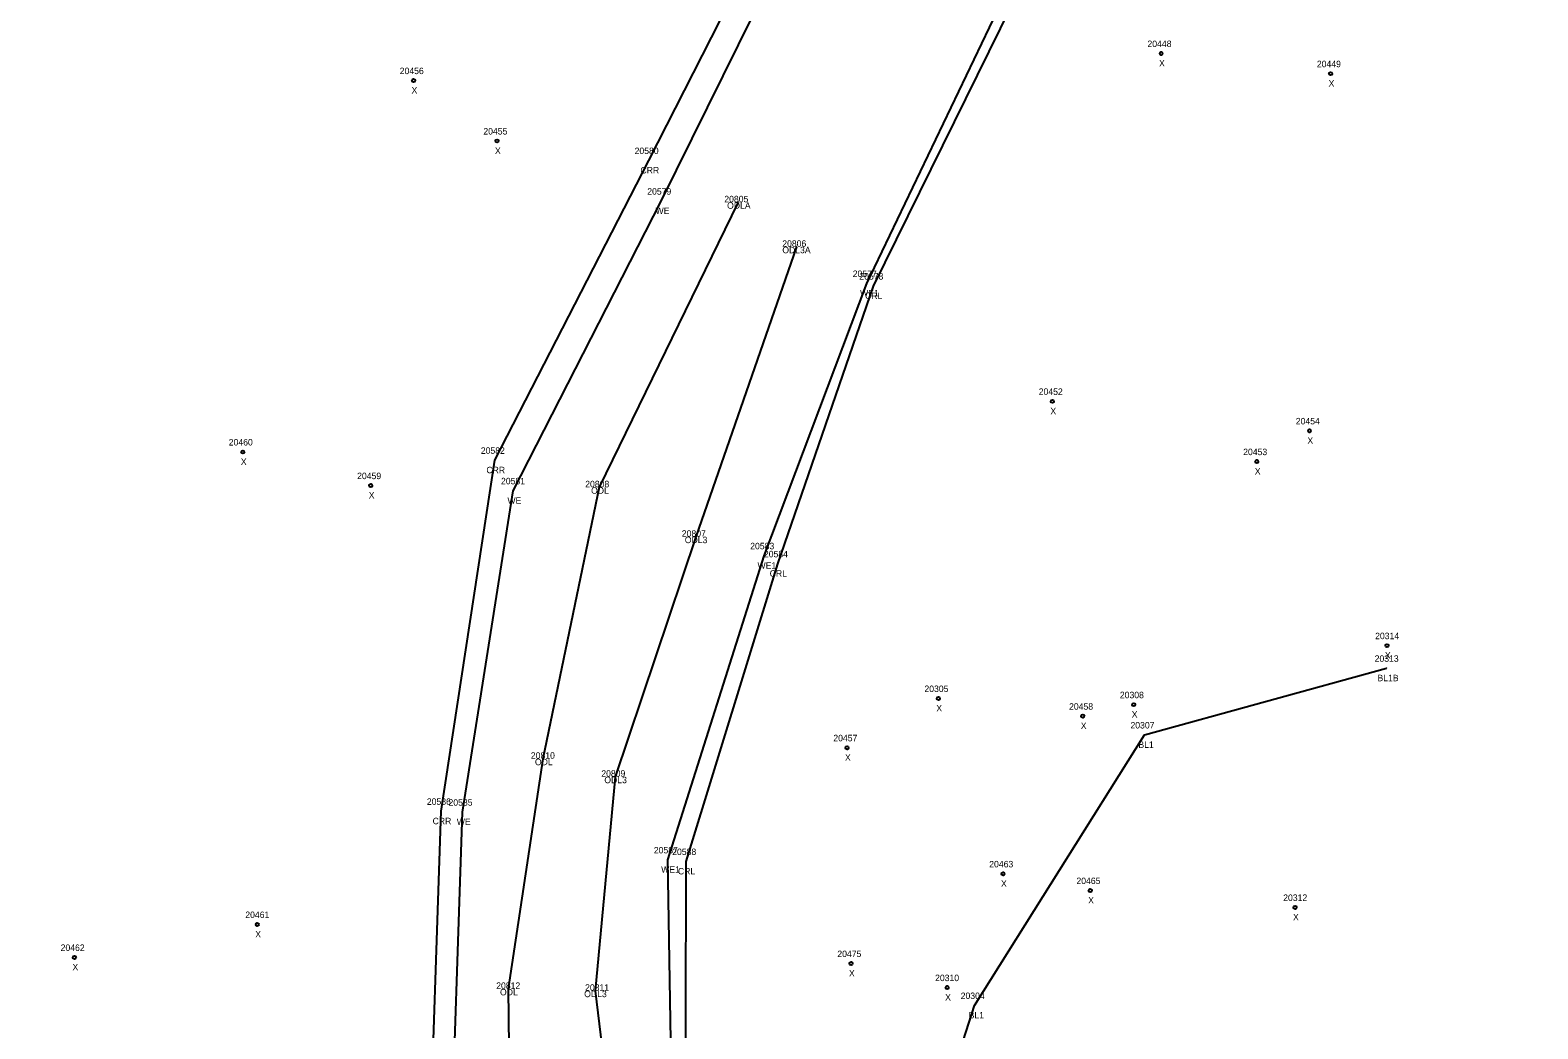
# Model space of a CAD drawing. Extents: x 1966740 to 1969291, y 1117378 to 1118461.
# Drawn here: x 1967728.3 to 1967961.6, y 1117958.8 to 1118113.2 of the extents above; entities that cross this region are included whole.
import ezdxf

# ---------------------------------------------------------------- set-up
doc = ezdxf.new("R2010")
doc.units = 0
for name, color, linetype in [('RD_DTM_BkLn1', 7, 'Continuous'), ('RD_EX_H2O', 7, 'Continuous'), ('RD_EX_H2O_txCode', 7, 'Continuous'), ('RD_SMD_Locator', 7, 'Continuous'), ('RD_SMD_Misc', 7, 'Continuous')]:
    doc.layers.add(name, color=color, linetype=linetype)

msp = doc.modelspace()

# ---------------------------------------------------------------- linework, layer by layer
at = {"layer": 'RD_DTM_BkLn1'}
msp.add_lwpolyline([(1967864.65, 1117932.01), (1967874.44, 1117962.38), (1967900.7, 1118004.22), (1967938.17, 1118014.53)], dxfattribs=at)
at = {"layer": 'RD_EX_H2O'}
for points in [[(1967852.4, 1118390.04), (1967912.21, 1118383.64), (1967925.08, 1118336.82), (1967944.14, 1118294.4), (1967946.67, 1118243.15), (1967961.58, 1118191.28), (1967922.84, 1118148.62), (1967880.18, 1118117.11), (1967858.72, 1118073.64), (1967843.96, 1118030.69), (1967829.77, 1117984.65), (1967829.63, 1117934.73), (1967834.65, 1117903.36)], [(1967852.05, 1118385.41), (1967898.77, 1118376.41), (1967924.08, 1118337.23), (1967939.81, 1118294.93), (1967943.5, 1118242.16), (1967952.29, 1118191.75), (1967920.83, 1118149.81), (1967879.07, 1118118.61), (1967857.7, 1118074.04), (1967841.84, 1118031.93), (1967826.93, 1117984.9), (1967827.73, 1117935.27), (1967832.39, 1117902.59), (1967835.81, 1117893.8), (1967842.37, 1117871.73), (1967853.33, 1117857.05), (1967865.72, 1117824.99), (1967870.38, 1117810.73), (1967864.06, 1117791.33)], [(1967848.72, 1118350.07), (1967881.79, 1118342.06), (1967895.58, 1118338.92), (1967907.43, 1118282.36), (1967910.66, 1118232.56), (1967917.99, 1118192.64), (1967910.91, 1118176.45), (1967849.83, 1118135.18), (1967825.91, 1118086.77), (1967802.99, 1118041.98), (1967795.15, 1117992.28), (1967793.27, 1117935.35), (1967800.64, 1117889.8), (1967800.4, 1117872.52), (1967800.8, 1117854.99), (1967811.67, 1117837.73), (1967837.15, 1117809.04), (1967808.01, 1117752.12)], [(1967848.54, 1118347.45), (1967880.38, 1118337.78), (1967886.93, 1118331.58), (1967896.4, 1118282.85), (1967906.33, 1118232.39), (1967914.38, 1118193.81), (1967904.29, 1118181.59), (1967847.52, 1118139.25), (1967823.99, 1118093.05), (1967800.15, 1118046.69), (1967791.83, 1117992.41), (1967789.93, 1117935.61), (1967798.32, 1117889.19), (1967796.67, 1117880.97)], [(1967837.87, 1118086.59), (1967816.35, 1118042.52), (1967807.65, 1118000.54), (1967802.25, 1117964.95), (1967802.7, 1117929.05), (1967808.24, 1117891.66), (1967818.1, 1117847.27), (1967841.92, 1117812.91), (1967830.83, 1117773.47), (1967807.55, 1117730.13), (1967792.1, 1117688.21), (1967759.2, 1117626.42), (1967746.8, 1117597.58), (1967728.31, 1117575.82), (1967748.97, 1117519.79), (1967787.59, 1117491.86), (1967802.7, 1117484.72), (1967813.63, 1117479.24)], [(1967846.86, 1118079.71), (1967831.29, 1118034.88), (1967818.84, 1117997.76), (1967815.72, 1117964.67), (1967820.18, 1117928.06), (1967829.19, 1117896.79), (1967834.11, 1117854.1), (1967863.47, 1117815.02), (1967842.32, 1117765.95), (1967826.02, 1117725.1), (1967807.77, 1117682.35), (1967775.42, 1117611.81), (1967754.74, 1117587.12), (1967745.94, 1117565.65), (1967761.23, 1117525.28), (1967787.1, 1117502.15), (1967805.18, 1117494.11), (1967821.41, 1117490.36)]]:
    msp.add_lwpolyline(points, dxfattribs=at)
at = {"layer": 'RD_SMD_Locator'}
for centre, radius in [((1967903.3, 1118109.6), 0.25), ((1967929.51, 1118106.48), 0.25), ((1967787.64, 1118105.41), 0.25), ((1967800.55, 1118096.07), 0.25), ((1967823.99, 1118093.05), 0.001), ((1967825.91, 1118086.77), 0.001), ((1967837.87, 1118086.59), 0.001), ((1967846.86, 1118079.71), 0.001), ((1967857.7, 1118074.04), 0.001), ((1967858.72, 1118073.64), 0.001), ((1967886.47, 1118055.81), 0.25), ((1967926.25, 1118051.25), 0.25), ((1967761.22, 1118047.98), 0.25), ((1967800.15, 1118046.69), 0.001), ((1967918.1, 1118046.49), 0.25), ((1967781.01, 1118042.78), 0.25), ((1967802.99, 1118041.98), 0.001), ((1967816.35, 1118042.52), 0.001), ((1967831.29, 1118034.88), 0.001), ((1967841.84, 1118031.93), 0.001), ((1967843.96, 1118030.69), 0.001), ((1967938.24, 1118018.03), 0.25), ((1967938.17, 1118014.53), 0.001), ((1967868.83, 1118009.86), 0.25), ((1967899.06, 1118008.9), 0.25), ((1967891.17, 1118007.13), 0.25), ((1967900.7, 1118004.22), 0.001), ((1967854.7, 1118002.24), 0.25), ((1967807.65, 1118000.54), 0.001), ((1967818.84, 1117997.76), 0.001), ((1967791.83, 1117992.41), 0.001), ((1967795.15, 1117992.28), 0.001), ((1967826.93, 1117984.9), 0.001), ((1967829.77, 1117984.65), 0.001), ((1967878.84, 1117982.74), 0.25), ((1967892.33, 1117980.16), 0.25), ((1967924.02, 1117977.55), 0.25), ((1967763.46, 1117974.91), 0.25), ((1967735.17, 1117969.82), 0.25), ((1967855.32, 1117968.87), 0.25), ((1967802.25, 1117964.95), 0.001), ((1967815.72, 1117964.67), 0.001), ((1967870.19, 1117965.15), 0.25), ((1967874.44, 1117962.38), 0.001)]:
    msp.add_circle(centre, radius, dxfattribs=at)

# ---------------------------------------------------------------- texts
at = {"layer": 'RD_EX_H2O_txCode'}
for s, p in [('20580', (1967821.83, 1118094.05)), ('CRR', (1967822.74, 1118091.05)), ('20579', (1967823.79, 1118087.77)), ('WE', (1967825.07, 1118084.77)), ('20805', (1967835.71, 1118086.59)), ('ODLA', (1967836.14, 1118085.59)), ('20806', (1967844.68, 1118079.71)), ('ODL3A', (1967844.68, 1118078.71)), ('20577', (1967855.58, 1118075.04)), ('20578', (1967856.6, 1118074.64)), ('WE1', (1967856.72, 1118072.04)), ('CRL', (1967857.49, 1118071.64)), ('20582', (1967798.04, 1118047.69)), ('CRR', (1967798.9, 1118044.69)), ('20581', (1967801.16, 1118042.98)), ('20808', (1967814.19, 1118042.52)), ('ODL', (1967815.1, 1118041.52)), ('WE', (1967802.16, 1118039.98)), ('20807', (1967829.14, 1118034.88)), ('ODL3', (1967829.6, 1118033.88)), ('20583', (1967839.72, 1118032.93)), ('20584', (1967841.84, 1118031.69)), ('WE1', (1967840.85, 1118029.93)), ('CRL', (1967842.73, 1118028.69)), ('20810', (1967805.78, 1118000.54)), ('ODL', (1967806.41, 1117999.54)), ('20809', (1967816.68, 1117997.76)), ('ODL3', (1967817.15, 1117996.76)), ('20586', (1967789.69, 1117993.41)), ('20585', (1967793.04, 1117993.28)), ('CRR', (1967790.58, 1117990.41)), ('WE', (1967794.32, 1117990.28)), ('20587', (1967824.81, 1117985.9)), ('20588', (1967827.65, 1117985.65)), ('WE1', (1967825.94, 1117982.9)), ('CRL', (1967828.54, 1117982.65)), ('20812', (1967800.42, 1117964.95)), ('ODL', (1967801.01, 1117963.95)), ('ODL3', (1967814.03, 1117963.67)), ('20811', (1967814.17, 1117964.67))]:
    msp.add_text(s, height=1, dxfattribs=at).set_placement(p)
at = {"layer": 'RD_SMD_Misc'}
for s, p in [('20448', (1967901.18, 1118110.6)), ('20456', (1967785.49, 1118106.41)), ('X', (1967902.98, 1118107.6)), ('20449', (1967927.39, 1118107.48)), ('X', (1967787.32, 1118103.41)), ('X', (1967929.2, 1118104.48)), ('20455', (1967798.43, 1118097.07)), ('X', (1967800.23, 1118094.07)), ('20452', (1967884.36, 1118056.81)), ('X', (1967886.16, 1118053.81)), ('20454', (1967924.13, 1118052.25)), ('20460', (1967759.04, 1118048.98)), ('20453', (1967915.99, 1118047.49)), ('X', (1967925.93, 1118049.25)), ('X', (1967760.91, 1118045.98)), ('20459', (1967778.9, 1118043.78)), ('X', (1967917.79, 1118044.49)), ('X', (1967780.7, 1118040.78)), ('20314', (1967936.4, 1118019.03)), ('20313', (1967936.33, 1118015.53)), ('X', (1967937.92, 1118016.03)), ('BL1B', (1967936.77, 1118012.53)), ('20305', (1967866.67, 1118010.86)), ('X', (1967868.51, 1118007.86)), ('20458', (1967889.05, 1118008.13)), ('20308', (1967896.91, 1118009.9)), ('X', (1967898.75, 1118006.9)), ('20457', (1967852.58, 1118003.24)), ('X', (1967890.86, 1118005.13)), ('20307', (1967898.55, 1118005.22)), ('BL1', (1967899.78, 1118002.22)), ('X', (1967854.38, 1118000.24)), ('20463', (1967876.7, 1117983.74)), ('X', (1967878.52, 1117980.74)), ('20465', (1967890.19, 1117981.16)), ('X', (1967892.01, 1117978.16)), ('20312', (1967922.18, 1117978.55)), ('20461', (1967761.6, 1117975.91)), ('X', (1967923.7, 1117975.55)), ('X', (1967763.14, 1117972.91)), ('20462', (1967733.03, 1117970.82)), ('20475', (1967853.2, 1117969.87)), ('X', (1967734.86, 1117967.82)), ('X', (1967855, 1117966.87)), ('20310', (1967868.32, 1117966.15)), ('20304', (1967872.28, 1117963.38)), ('X', (1967869.88, 1117963.15)), ('BL1', (1967873.51, 1117960.38))]:
    msp.add_text(s, height=1, dxfattribs=at).set_placement(p)

doc.saveas('drawing.dxf')
